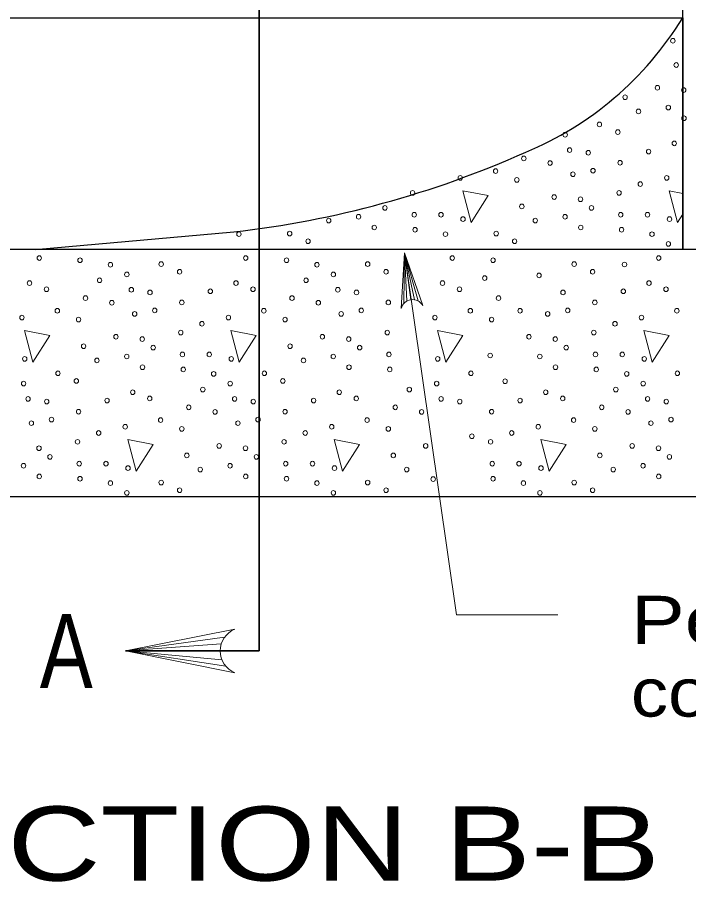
# Model space of a CAD drawing. Extents: x -410.5 to -376.5, y 1617.6 to 1661.6.
# Drawn here: x -393.247 to -391.077, y 1628.899 to 1631.696 of the extents above; entities that cross this region are included whole.
import ezdxf
from ezdxf.enums import TextEntityAlignment as Align

# ---------------------------------------------------------------- set-up
doc = ezdxf.new("R2010")
doc.units = 0
doc.header["$LTSCALE"] = 0.062
doc.layers.add('1', color=7, linetype='Continuous', lineweight=13)

msp = doc.modelspace()

# ---------------------------------------------------------------- linework, layer by layer
at = {"layer": '1', "lineweight": 35}
for p, q in [((-392.4645, 1629.795), (-392.4645, 1634.16592)), ((-392.4645, 1629.64583), (-392.4645, 1629.795)), ((-392.4645, 1629.64583), (-392.89717, 1629.64583))]:
    msp.add_line(p, q, dxfattribs=at)
at = {"layer": '1', "lineweight": 25}
for p, q in [((-393.83325, 1631.69458), (-391.09567, 1631.69458)), ((-393.18867, 1630.94508), (-392.54683, 1631.00208))]:
    msp.add_line(p, q, dxfattribs=at)
at = {"layer": '1'}
for p, q in [((-391.09567, 1631.12633), (-391.1395, 1631.13492)), ((-391.9975, 1630.77008), (-391.99483, 1630.93408)), ((-391.97417, 1630.78225), (-391.99483, 1630.93408)), ((-391.988, 1630.7775), (-391.99483, 1630.93408)), ((-391.96267, 1630.78217), (-391.99483, 1630.93408)), ((-391.951, 1630.77833), (-391.99483, 1630.93408)), ((-392.57667, 1629.69067), (-392.89717, 1629.64583)), ((-392.5875, 1629.6685), (-392.89717, 1629.64583)), ((-392.59083, 1629.64583), (-392.89717, 1629.64583)), ((-392.58517, 1629.617), (-392.89717, 1629.64583)), ((-392.57283, 1629.59625), (-392.89717, 1629.64583))]:
    msp.add_line(p, q, dxfattribs=at)
at = {"layer": '1', "lineweight": 25}
for points in [[(-391.09567, 1634.05167), (-391.07275, 1634.05717), (-390.86258, 1634.005), (-390.75258, 1634.02892), (-390.70333, 1634.03392), (-390.53658, 1634.02533), (-390.38608, 1633.99358), (-390.15167, 1634.0215), (-390.15167, 1630.94508), (-391.09567, 1630.94508)], [(-391.09567, 1630.94508), (-391.09567, 1631.69458), (-391.09567, 1634.05167)], [(-391.09567, 1631.69458), (-391.09567, 1630.94508), (-393.18867, 1630.94508)], [(-395.15925, 1630.79517), (-394.77725, 1630.79517), (-394.77725, 1630.1455), (-390.15167, 1630.1455), (-390.15167, 1630.94508), (-394.16367, 1630.94508), (-394.16367, 1630.79517), (-393.83325, 1630.79517), (-393.83325, 1630.64525), (-394.27908, 1630.64525), (-394.54583, 1630.79517), (-394.77725, 1630.79517)]]:
    msp.add_lwpolyline(points, dxfattribs=at)
at = {"layer": '1'}
for points in [[(-391.807, 1631.13492), (-391.78, 1631.0325), (-391.725, 1631.11892)], [(-393.22367, 1630.68292), (-393.19667, 1630.58042), (-393.14167, 1630.66692)], [(-392.55608, 1630.68292), (-392.52917, 1630.58042), (-392.47425, 1630.66692)], [(-391.88858, 1630.68292), (-391.86167, 1630.58042), (-391.80667, 1630.66692)], [(-391.22117, 1630.68292), (-391.19417, 1630.58042), (-391.13917, 1630.66692)], [(-392.88992, 1630.3295), (-392.86292, 1630.22717), (-392.80792, 1630.31358)], [(-392.22242, 1630.3295), (-392.19542, 1630.22717), (-392.14042, 1630.31358)], [(-391.55483, 1630.3295), (-391.52783, 1630.22717), (-391.47292, 1630.31358)]]:
    msp.add_lwpolyline(points, close=True, dxfattribs=at)
for points in [[(-391.1395, 1631.13492), (-391.1125, 1631.0325), (-391.09567, 1631.059)], [(-392.00608, 1630.75383), (-391.99483, 1630.93408), (-391.93592, 1630.7635)], [(-391.99483, 1630.93408), (-391.82733, 1629.763), (-391.49925, 1629.763)], [(-392.54317, 1629.575), (-392.89717, 1629.64583), (-392.54317, 1629.71658)]]:
    msp.add_lwpolyline(points, dxfattribs=at)
for centre, radius, start, end in [((-391.96897, 1630.74451), 0.0382, 29.85022, 165.67635), ((-392.51454, 1629.64588), 0.0764, 112.08782, 247.91395)]:
    msp.add_arc(centre, radius, start, end, dxfattribs=at)
at = {"layer": '1', "lineweight": 25}
for centre, major_axis, start_param, end_param in [((-391.98484, 1632.30872), (0, 1.12397), 3.5092821, 4.1343748), ((-392.89445, 1634.49322), (0, -3.51046), 0.105032, 0.4000009)]:
    msp.add_ellipse(centre, major_axis=major_axis, ratio=0.944543, start_param=start_param, end_param=end_param, dxfattribs=at)
at = {"layer": '1'}
for centre, major_axis in [((-391.12767, 1631.61989), (0, 0.00756)), ((-391.11693, 1631.54163), (0, 0.00756)), ((-391.17756, 1631.4679), (0, 0.00756)), ((-391.09251, 1631.46053), (0, 0.00756)), ((-391.28208, 1631.43733), (0, 0.00756)), ((-391.23881, 1631.39151), (0, 0.00756)), ((-391.14241, 1631.40394), (0, 0.00756)), ((-391.09162, 1631.36925), (0, -0.00756)), ((-391.36502, 1631.34952), (0, -0.00756)), ((-391.47588, 1631.31613), (0, 0.00756)), ((-391.30556, 1631.32473), (0, -0.00756)), ((-391.12316, 1631.28816), (0, -0.00756)), ((-391.46142, 1631.26654), (0, 0.00756)), ((-391.40107, 1631.25789), (0, -0.00756)), ((-391.2061, 1631.26148), (0, -0.00756)), ((-391.60955, 1631.23951), (0, 0.00756)), ((-391.52456, 1631.22456), (0, 0.00756)), ((-391.29833, 1631.22544), (0, -0.00756)), ((-391.70061, 1631.19847), (0, 0.00756)), ((-391.38577, 1631.19976), (0, -0.00756)), ((-391.81503, 1631.1765), (0, -0.00756)), ((-391.63208, 1631.16984), (0, 0.00756)), ((-391.45069, 1631.18828), (0, 0.00756)), ((-391.14753, 1631.1765), (0, -0.00756)), ((-391.23319, 1631.15648), (0, -0.00756)), ((-391.96912, 1631.12785), (0, -0.00756)), ((-391.51132, 1631.11455), (0, 0.00756)), ((-391.30161, 1631.12785), (0, -0.00756)), ((-391.61584, 1631.08398), (0, 0.00756)), ((-391.42627, 1631.10718), (0, 0.00756)), ((-392.05834, 1631.07921), (0, -0.00756)), ((-391.96372, 1631.05724), (0, -0.00756)), ((-391.87717, 1631.05724), (0, 0.00756)), ((-391.39083, 1631.07921), (0, -0.00756)), ((-391.29621, 1631.05724), (0, -0.00756)), ((-391.20966, 1631.05724), (0, 0.00756)), ((-392.24007, 1631.03816), (0, 0.00756)), ((-392.14367, 1631.05059), (0, 0.00756)), ((-391.80602, 1631.04293), (0, -0.00756)), ((-391.57256, 1631.03816), (0, 0.00756)), ((-391.47616, 1631.05059), (0, 0.00756)), ((-391.13851, 1631.04293), (0, -0.00756)), ((-392.09288, 1631.0159), (0, -0.00756)), ((-391.96105, 1631.0086), (0, -0.00756)), ((-391.42538, 1631.0159), (0, -0.00756)), ((-391.29354, 1631.0086), (0, -0.00756)), ((-392.53027, 1630.99429), (0, 0.00756)), ((-392.36628, 1630.99617), (0, -0.00756)), ((-391.86276, 1630.99429), (0, 0.00756)), ((-391.69878, 1630.99617), (0, -0.00756)), ((-391.19525, 1630.99429), (0, 0.00756)), ((-392.30682, 1630.97138), (0, -0.00756)), ((-391.63931, 1630.97138), (0, -0.00756)), ((-391.14213, 1630.96278), (0, 0.00756)), ((-393.17581, 1630.91719), (0, -0.00756)), ((-392.5083, 1630.91719), (0, -0.00756)), ((-391.84079, 1630.91719), (0, -0.00756)), ((-391.17328, 1630.91719), (0, -0.00756)), ((-393.04397, 1630.90989), (0, -0.00756)), ((-392.94568, 1630.89558), (0, 0.00756)), ((-392.7817, 1630.89746), (0, -0.00756)), ((-392.37647, 1630.90989), (0, -0.00756)), ((-392.27818, 1630.89558), (0, 0.00756)), ((-392.11419, 1630.89746), (0, -0.00756)), ((-391.70896, 1630.90989), (0, -0.00756)), ((-391.44668, 1630.89746), (0, -0.00756)), ((-391.2839, 1630.89616), (0, 0.00756)), ((-392.89256, 1630.86407), (0, 0.00756)), ((-392.72224, 1630.87267), (0, -0.00756)), ((-392.22505, 1630.86407), (0, 0.00756)), ((-392.05473, 1630.87267), (0, -0.00756)), ((-391.56027, 1630.86101), (0, 0.00756)), ((-391.38722, 1630.87267), (0, -0.00756)), ((-393.20735, 1630.83609), (0, -0.00756)), ((-392.98089, 1630.84499), (0, 0.00756)), ((-392.53984, 1630.83609), (0, -0.00756)), ((-392.31339, 1630.84499), (0, 0.00756)), ((-391.87233, 1630.83609), (0, -0.00756)), ((-391.73573, 1630.85223), (0, 0.00756)), ((-391.20482, 1630.83609), (0, -0.00756)), ((-393.15239, 1630.81607), (0, -0.00756)), ((-392.8781, 1630.81448), (0, 0.00756)), ((-392.81774, 1630.80582), (0, -0.00756)), ((-392.62278, 1630.80942), (0, -0.00756)), ((-392.48488, 1630.81607), (0, -0.00756)), ((-392.21059, 1630.81448), (0, 0.00756)), ((-392.15024, 1630.80582), (0, -0.00756)), ((-391.81737, 1630.81607), (0, -0.00756)), ((-391.48273, 1630.80582), (0, -0.00756)), ((-391.28776, 1630.80942), (0, -0.00756)), ((-391.14986, 1630.81607), (0, -0.00756)), ((-393.02623, 1630.78745), (0, 0.00756)), ((-392.35872, 1630.78745), (0, 0.00756)), ((-391.69121, 1630.78745), (0, 0.00756)), ((-392.94123, 1630.77249), (0, 0.00756)), ((-392.715, 1630.77338), (0, -0.00756)), ((-392.27372, 1630.77249), (0, 0.00756)), ((-392.0475, 1630.77338), (0, -0.00756)), ((-391.37999, 1630.77338), (0, -0.00756)), ((-393.23171, 1630.72444), (0, -0.00756)), ((-393.11729, 1630.7464), (0, 0.00756)), ((-392.86736, 1630.73621), (0, 0.00756)), ((-392.80245, 1630.7477), (0, -0.00756)), ((-392.5642, 1630.72444), (0, -0.00756)), ((-392.44978, 1630.7464), (0, 0.00756)), ((-392.19985, 1630.73621), (0, 0.00756)), ((-392.13494, 1630.7477), (0, -0.00756)), ((-391.89669, 1630.72444), (0, -0.00756)), ((-391.78227, 1630.7464), (0, 0.00756)), ((-391.62168, 1630.74678), (0, 0.00756)), ((-391.53235, 1630.73621), (0, 0.00756)), ((-391.46743, 1630.7477), (0, -0.00756)), ((-391.22919, 1630.72444), (0, -0.00756)), ((-391.11476, 1630.7464), (0, 0.00756)), ((-393.04876, 1630.71778), (0, 0.00756)), ((-392.64987, 1630.70441), (0, -0.00756)), ((-392.38125, 1630.71778), (0, 0.00756)), ((-391.71374, 1630.71778), (0, 0.00756)), ((-391.31485, 1630.70441), (0, -0.00756)), ((-392.71829, 1630.67579), (0, -0.00756)), ((-392.05078, 1630.67579), (0, -0.00756)), ((-391.38327, 1630.67579), (0, -0.00756)), ((-392.92799, 1630.66248), (0, 0.00756)), ((-392.84294, 1630.65512), (0, 0.00756)), ((-392.26049, 1630.66248), (0, 0.00756)), ((-392.17543, 1630.65512), (0, 0.00756)), ((-391.59298, 1630.66248), (0, 0.00756)), ((-391.50793, 1630.65512), (0, 0.00756)), ((-393.03252, 1630.63192), (0, 0.00756)), ((-392.80751, 1630.62715), (0, -0.00756)), ((-392.36501, 1630.63192), (0, 0.00756)), ((-392.14, 1630.62715), (0, -0.00756)), ((-391.47249, 1630.62715), (0, -0.00756)), ((-393.2227, 1630.59087), (0, -0.00756)), ((-392.98924, 1630.5861), (0, 0.00756)), ((-392.89284, 1630.59853), (0, 0.00756)), ((-392.71289, 1630.60518), (0, -0.00756)), ((-392.62634, 1630.60518), (0, 0.00756)), ((-392.55519, 1630.59087), (0, -0.00756)), ((-392.32173, 1630.5861), (0, 0.00756)), ((-392.22533, 1630.59853), (0, 0.00756)), ((-392.04538, 1630.60518), (0, -0.00756)), ((-391.88768, 1630.59087), (0, -0.00756)), ((-391.71819, 1630.6018), (0, 0.00756)), ((-391.55782, 1630.59853), (0, 0.00756)), ((-391.37787, 1630.60518), (0, -0.00756)), ((-391.29132, 1630.60518), (0, 0.00756)), ((-391.22017, 1630.59087), (0, -0.00756)), ((-392.84205, 1630.56384), (0, -0.00756)), ((-392.71022, 1630.55654), (0, -0.00756)), ((-392.17454, 1630.56384), (0, -0.00756)), ((-392.04271, 1630.55654), (0, -0.00756)), ((-391.50704, 1630.56384), (0, -0.00756)), ((-391.3752, 1630.55654), (0, -0.00756)), ((-393.11545, 1630.54411), (0, -0.00756)), ((-392.61193, 1630.54223), (0, 0.00756)), ((-392.44794, 1630.54411), (0, -0.00756)), ((-391.78044, 1630.54411), (0, -0.00756)), ((-391.27691, 1630.54223), (0, 0.00756)), ((-391.11293, 1630.54411), (0, -0.00756)), ((-393.22632, 1630.51072), (0, 0.00756)), ((-393.05599, 1630.51932), (0, -0.00756)), ((-392.55881, 1630.51072), (0, 0.00756)), ((-392.38848, 1630.51932), (0, -0.00756)), ((-391.8913, 1630.51072), (0, 0.00756)), ((-391.66993, 1630.51832), (0, 0.00756)), ((-391.22379, 1630.51072), (0, 0.00756)), ((-392.87359, 1630.48274), (0, -0.00756)), ((-392.64714, 1630.49164), (0, 0.00756)), ((-392.20608, 1630.48274), (0, -0.00756)), ((-391.97963, 1630.49164), (0, 0.00756)), ((-391.53858, 1630.48274), (0, -0.00756)), ((-391.31212, 1630.49164), (0, 0.00756)), ((-393.21185, 1630.46113), (0, 0.00756)), ((-393.1515, 1630.45247), (0, -0.00756)), ((-392.95653, 1630.45607), (0, -0.00756)), ((-392.81863, 1630.46272), (0, -0.00756)), ((-392.54434, 1630.46113), (0, 0.00756)), ((-392.48399, 1630.45247), (0, -0.00756)), ((-392.28902, 1630.45607), (0, -0.00756)), ((-392.15113, 1630.46272), (0, -0.00756)), ((-391.87684, 1630.46113), (0, 0.00756)), ((-391.81648, 1630.45247), (0, -0.00756)), ((-391.62151, 1630.45607), (0, -0.00756)), ((-391.48362, 1630.46272), (0, -0.00756)), ((-391.20933, 1630.46113), (0, 0.00756)), ((-391.14897, 1630.45247), (0, -0.00756)), ((-393.04876, 1630.42003), (0, -0.00756)), ((-392.69248, 1630.4341), (0, 0.00756)), ((-392.60748, 1630.41914), (0, 0.00756)), ((-392.38125, 1630.42003), (0, -0.00756)), ((-392.02497, 1630.4341), (0, 0.00756)), ((-391.93997, 1630.41914), (0, 0.00756)), ((-391.71374, 1630.42003), (0, -0.00756)), ((-391.35746, 1630.4341), (0, 0.00756)), ((-391.27246, 1630.41914), (0, 0.00756)), ((-393.1362, 1630.39435), (0, -0.00756)), ((-392.78353, 1630.39305), (0, 0.00756)), ((-392.46869, 1630.39435), (0, -0.00756)), ((-392.11603, 1630.39305), (0, 0.00756)), ((-391.44852, 1630.39305), (0, 0.00756)), ((-391.13368, 1630.39435), (0, -0.00756)), ((-393.20112, 1630.38286), (0, 0.00756)), ((-392.89796, 1630.37109), (0, -0.00756)), ((-392.715, 1630.36443), (0, 0.00756)), ((-392.53361, 1630.38286), (0, 0.00756)), ((-392.23045, 1630.37109), (0, -0.00756)), ((-392.0475, 1630.36443), (0, 0.00756)), ((-391.56294, 1630.37109), (0, -0.00756)), ((-391.37999, 1630.36443), (0, 0.00756)), ((-391.19859, 1630.38286), (0, 0.00756)), ((-392.98362, 1630.35106), (0, -0.00756)), ((-392.31611, 1630.35106), (0, -0.00756)), ((-391.77741, 1630.34039), (0, 0.00756)), ((-391.6486, 1630.35106), (0, -0.00756)), ((-393.1767, 1630.30177), (0, 0.00756)), ((-393.05204, 1630.32244), (0, -0.00756)), ((-392.59424, 1630.30913), (0, 0.00756)), ((-392.50919, 1630.30177), (0, 0.00756)), ((-392.38453, 1630.32244), (0, -0.00756)), ((-391.92673, 1630.30913), (0, 0.00756)), ((-391.71702, 1630.32244), (0, -0.00756)), ((-391.25922, 1630.30913), (0, 0.00756)), ((-391.17417, 1630.30177), (0, 0.00756)), ((-393.14126, 1630.2738), (0, -0.00756)), ((-392.69876, 1630.27857), (0, 0.00756)), ((-392.47376, 1630.2738), (0, -0.00756)), ((-392.03125, 1630.27857), (0, 0.00756)), ((-391.36374, 1630.27857), (0, 0.00756)), ((-391.13874, 1630.2738), (0, -0.00756)), ((-393.22659, 1630.24518), (0, 0.00756)), ((-393.04664, 1630.25183), (0, -0.00756)), ((-392.96009, 1630.25183), (0, 0.00756)), ((-392.55908, 1630.24518), (0, 0.00756)), ((-392.37914, 1630.25183), (0, -0.00756)), ((-392.29258, 1630.25183), (0, 0.00756)), ((-391.71163, 1630.25183), (0, -0.00756)), ((-391.62507, 1630.25183), (0, 0.00756)), ((-391.22407, 1630.24518), (0, 0.00756)), ((-392.88895, 1630.23752), (0, -0.00756)), ((-392.65548, 1630.23275), (0, 0.00756)), ((-392.22144, 1630.23752), (0, -0.00756)), ((-391.98798, 1630.23275), (0, 0.00756)), ((-391.55393, 1630.23752), (0, -0.00756)), ((-391.32047, 1630.23275), (0, 0.00756)), ((-393.17581, 1630.21049), (0, -0.00756)), ((-393.04397, 1630.20319), (0, -0.00756)), ((-392.94568, 1630.18888), (0, 0.00756)), ((-392.7817, 1630.19076), (0, -0.00756)), ((-392.5083, 1630.21049), (0, -0.00756)), ((-392.37647, 1630.20319), (0, -0.00756)), ((-392.27818, 1630.18888), (0, 0.00756)), ((-392.11419, 1630.19076), (0, -0.00756)), ((-391.90243, 1630.202), (0, 0.00756)), ((-391.70896, 1630.20319), (0, -0.00756)), ((-391.61067, 1630.18888), (0, 0.00756)), ((-391.44668, 1630.19076), (0, -0.00756)), ((-391.17328, 1630.21049), (0, -0.00756)), ((-392.72224, 1630.16597), (0, -0.00756)), ((-392.05473, 1630.16597), (0, -0.00756)), ((-391.38722, 1630.16597), (0, -0.00756)), ((-392.89256, 1630.15737), (0, 0.00756)), ((-392.22505, 1630.15737), (0, 0.00756)), ((-391.55754, 1630.15737), (0, 0.00756))]:
    msp.add_ellipse(centre, major_axis=major_axis, ratio=0.944543, dxfattribs=at)

# ---------------------------------------------------------------- texts
for s, height, width, p in [('Permissible', 0.156, 1.25, (-391.26325, 1629.66825)), ('const. joint', 0.156, 1.15, (-391.26325, 1629.43358)), ('SECTION B-B', 0.24, 1.3, (-393.83558, 1628.90275))]:
    msp.add_text(s, height=height, dxfattribs=dict(at, width=width)).set_placement(p)
at = {"layer": '1', "width": 0.8}
msp.add_text('A', height=0.24, dxfattribs=at).set_placement((-393.08842, 1629.52575), align=Align.CENTER)

doc.saveas('drawing.dxf')
